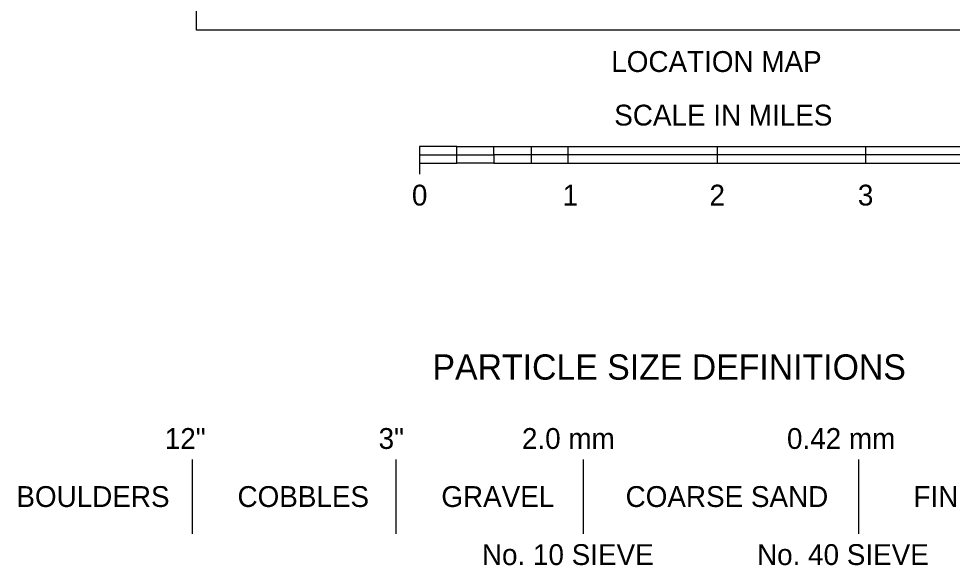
# Model space of a CAD drawing. Extents: x 0 to 34, y 0 to 22.
# Drawn here: x 22.22 to 28.5, y 10.41 to 14.08 of the extents above; entities that cross this region are included whole.
import ezdxf

# ---------------------------------------------------------------- set-up
doc = ezdxf.new("R2010")
doc.units = 0
doc.layers.add('SH_Data', color=7, linetype='Continuous')
doc.layers.add('SH_Text', color=7, linetype='Continuous')

msp = doc.modelspace()

# ---------------------------------------------------------------- linework, layer by layer
at = {"layer": 'SH_Data'}
for p, q in [((25.1667, 13.22), (24.9167, 13.22)), ((24.9167, 13.22), (24.9167, 13.1638)), ((25.1667, 13.22), (25.4167, 13.22)), ((25.1667, 13.1638), (25.1667, 13.22)), ((25.4167, 13.1638), (25.4167, 13.22)), ((25.4167, 13.22), (25.6667, 13.22)), ((25.6667, 13.22), (25.9167, 13.22)), ((25.6667, 13.22), (25.6667, 13.1638)), ((25.9167, 13.1638), (25.9167, 13.22)), ((25.9167, 13.22), (26.9167, 13.22)), ((26.9167, 13.22), (26.9167, 13.1638)), ((26.9167, 13.22), (27.9167, 13.22)), ((27.9167, 13.1638), (27.9167, 13.22)), ((27.9167, 13.22), (28.9167, 13.22)), ((24.9167, 13.1638), (24.9167, 13.0325)), ((24.9167, 13.1638), (25.1667, 13.1638)), ((25.1667, 13.1638), (25.4167, 13.1638)), ((25.1667, 13.1075), (25.1667, 13.1638)), ((25.4167, 13.1638), (25.4167, 13.1075)), ((25.6667, 13.1638), (25.4167, 13.1638)), ((25.9167, 13.1638), (25.6667, 13.1638)), ((25.6667, 13.1638), (25.6667, 13.1075)), ((25.9167, 13.1075), (25.9167, 13.1638)), ((26.9167, 13.1638), (25.9167, 13.1638)), ((27.9167, 13.1638), (26.9167, 13.1638)), ((26.9167, 13.1638), (26.9167, 13.1075)), ((27.9167, 13.1075), (27.9167, 13.1638)), ((28.9167, 13.1638), (27.9167, 13.1638)), ((24.9167, 13.1075), (25.1667, 13.1075)), ((25.4167, 13.1075), (25.1667, 13.1075)), ((25.4167, 13.1075), (25.6667, 13.1075)), ((25.6667, 13.1075), (25.9167, 13.1075)), ((25.9167, 13.1075), (26.9167, 13.1075)), ((26.9167, 13.1075), (27.9167, 13.1075)), ((27.9167, 13.1075), (28.9167, 13.1075)), ((23.3896, 10.6173), (23.3896, 11.1173)), ((24.7596, 10.6173), (24.7596, 11.1173)), ((26.0196, 10.6173), (26.0196, 11.1173)), ((27.8696, 10.6173), (27.8696, 11.1173))]:
    msp.add_line(p, q, dxfattribs=at)
msp.add_lwpolyline([(23.4167, 21), (30.4167, 21), (30.4167, 14), (23.4167, 14)], close=True, dxfattribs=at)

# ---------------------------------------------------------------- texts
at = {"layer": 'SH_Text'}
for s, height, p in [('LOCATION MAP', 0.14, (26.2057, 13.72)), ('SCALE IN MILES', 0.14, (26.2256, 13.36)), ('0', 0.14, (24.8651, 12.8225)), ('1', 0.14, (25.8782, 12.8225)), ('2', 0.14, (26.866, 12.8225)), ('3', 0.14, (27.8639, 12.8225)), ('PARTICLE SIZE DEFINITIONS', 0.17, (25.0035, 11.6525)), ('12"', 0.14, (23.2034, 11.1873)), ('3"', 0.14, (24.6411, 11.1873)), ('2.0 mm', 0.14, (25.6049, 11.1873)), ('0.42 mm', 0.14, (27.3872, 11.1873)), ('BOULDERS', 0.14, (22.2054, 10.7973)), ('COBBLES', 0.14, (23.6923, 10.7973)), ('GRAVEL', 0.14, (25.0628, 10.7973)), ('COARSE SAND', 0.14, (26.3019, 10.7973)), ('FINE SAND', 0.14, (28.238, 10.7973)), ('No. 10 SIEVE', 0.14, (25.3358, 10.4073)), ('No. 40 SIEVE', 0.14, (27.1858, 10.4073))]:
    msp.add_text(s, height=height, dxfattribs=at).set_placement(p)

doc.saveas('drawing.dxf')
